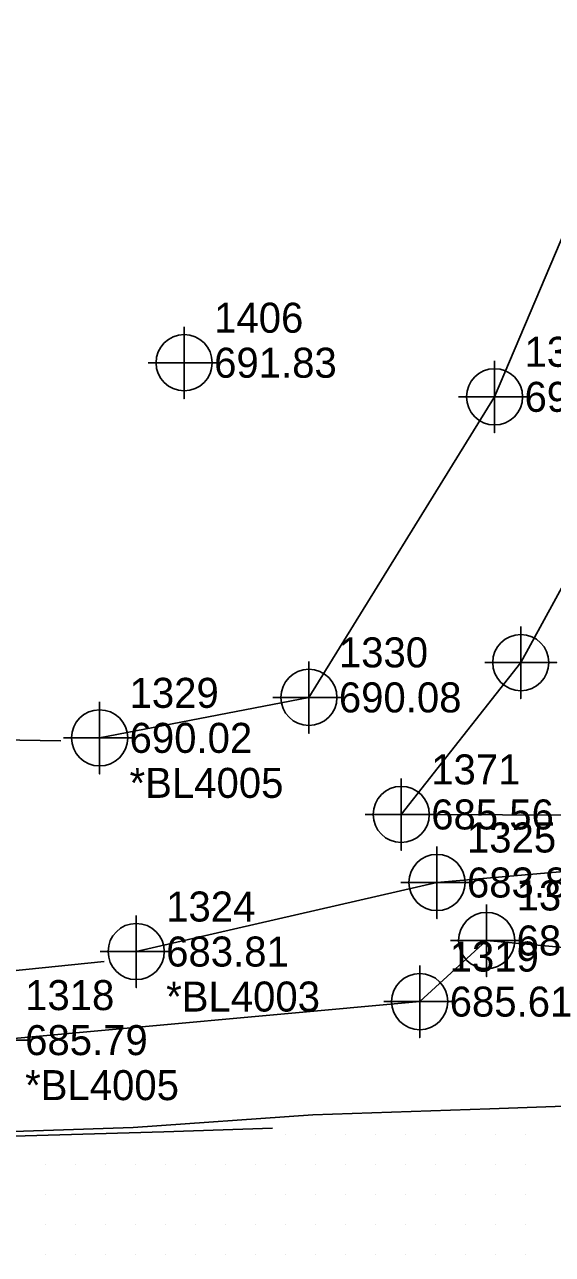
# Model space of a CAD drawing. Extents: x 1755643 to 1760494, y 736519 to 737621.
# Drawn here: x 1759022 to 1759066, y 737021.2 to 737123.7 of the extents above; entities that cross this region are included whole.
import ezdxf

# ---------------------------------------------------------------- set-up
doc = ezdxf.new("R2010")
doc.units = 0
for name, color, linetype in [('Exist Horizontal Alignment Curve and Spiral Data', 7, 'Continuous'), ('Exist Horizontal Alignment Direction Label', 7, 'Continuous'), ('Exist Railroads Standard Gauge', 7, 'Continuous'), ('Exist Roads EOT', 7, 'Continuous'), ('Old_Level_1', 7, 'Continuous'), ('Old_Level_10', 7, 'Continuous'), ('Old_Level_2', 7, 'Continuous'), ('Old_Level_3', 7, 'Continuous'), ('Prop Dimension', 7, 'Continuous'), ('Prop EOT Dash', 7, 'Continuous'), ('Prop Horizontal Alignment Direction Label', 7, 'Continuous'), ('Prop Lane Lines', 7, 'Continuous'), ('Prop Paved Shoulder', 7, 'Continuous'), ('Scratch_Level_1', 7, 'Continuous'), ('Scratch_Level_2', 7, 'Continuous'), ('Scratch_Level_5', 7, 'Continuous'), ('Scratch_Level_9', 7, 'Continuous')]:
    doc.layers.add(name, color=color, linetype=linetype)

msp = doc.modelspace()

# ---------------------------------------------------------------- linework, layer by layer
at = {"layer": 'Exist Horizontal Alignment Curve and Spiral Data'}
msp.add_lwpolyline([(1759035.3, 737098.53), (1759035.3, 737092.53), (1759035.3, 737095.53), (1759038.3, 737095.53), (1759032.3, 737095.53)], dxfattribs=at)
msp.add_circle((1759035.3, 737095.53), 2.34, dxfattribs=at)
at = {"layer": 'Exist Railroads Standard Gauge'}
for points in [[(1758977.85, 737203.59), (1758987.5, 737179.86), (1758991.58, 737151.56), (1758993.69, 737140.49), (1758995.27, 737131.26), (1758994.94, 737115.25), (1758984.91, 737087.23), (1758984.77, 737081.67), (1758987.54, 737075.38), (1758993.17, 737069.59), (1759001.68, 737066.26), (1759013.02, 737064.22), (1759025.02, 737064.03)], [(1758952.65, 737199.89), (1758952.65, 737198.86), (1758953.36, 737193.03), (1758954.04, 737179.81), (1758954.34, 737164.36), (1758955.22, 737148.98), (1758955.34, 737133.89), (1758956.84, 737119.49), (1758957.44, 737106.09), (1758959.04, 737092.09), (1758960.34, 737077.94), (1758963.11, 737068.15), (1758967.12, 737060.78), (1758972.3, 737056.45), (1758977.25, 737052.33), (1758982.37, 737047.65), (1758986.66, 737042.66), (1758993.87, 737041.05), (1759014.17, 737044.19), (1759028.62, 737045.64)]]:
    msp.add_lwpolyline(points, dxfattribs=at)
at = {"layer": 'Old_Level_10'}
for points in [[(1759056.38, 737055.23), (1759056.38, 737049.23), (1759056.38, 737052.23), (1759059.38, 737052.23), (1759053.38, 737052.23)], [(1759031.3, 737049.48), (1759031.3, 737043.48), (1759031.3, 737046.48), (1759034.3, 737046.48), (1759028.3, 737046.48)]]:
    msp.add_lwpolyline(points, dxfattribs=at)
for centre in [(1759056.38, 737052.23), (1759031.3, 737046.48)]:
    msp.add_circle(centre, 2.34, dxfattribs=at)
at = {"layer": 'Prop Dimension'}
msp.add_lwpolyline([(1759031.3, 737046.48), (1759056.38, 737052.23), (1759070.78, 737053.47), (1759077.3, 737052.76), (1759083.84, 737053.56)], dxfattribs=at)
at = {"layer": 'Prop Lane Lines'}
for points in [[(1759061.18, 737095.69), (1759061.18, 737089.69), (1759061.18, 737092.69), (1759064.18, 737092.69), (1759058.18, 737092.69)], [(1759063.37, 737073.55), (1759063.37, 737067.55), (1759063.37, 737070.55), (1759066.37, 737070.55), (1759060.37, 737070.55)], [(1759045.7, 737070.65), (1759045.7, 737064.65), (1759045.7, 737067.65), (1759048.7, 737067.65), (1759042.7, 737067.65)], [(1759028.25, 737067.28), (1759028.25, 737061.28), (1759028.25, 737064.28), (1759031.25, 737064.28), (1759025.25, 737064.28)], [(1759053.4, 737060.9), (1759053.4, 737054.9), (1759053.4, 737057.9), (1759056.4, 737057.9), (1759050.4, 737057.9)], [(1759060.52, 737050.4), (1759060.52, 737044.4), (1759060.52, 737047.4), (1759063.52, 737047.4), (1759057.52, 737047.4)], [(1759054.94, 737045.31), (1759054.94, 737039.31), (1759054.94, 737042.31), (1759057.94, 737042.31), (1759051.94, 737042.31)], [(1759019.54, 737042.1), (1759019.54, 737036.1), (1759019.54, 737039.1), (1759022.54, 737039.1), (1759016.54, 737039.1)]]:
    msp.add_lwpolyline(points, dxfattribs=at)
for centre in [(1759061.18, 737092.69), (1759063.37, 737070.55), (1759045.7, 737067.65), (1759028.25, 737064.28), (1759053.4, 737057.9), (1759060.52, 737047.4), (1759054.94, 737042.31)]:
    msp.add_circle(centre, 2.34, dxfattribs=at)
at = {"layer": 'Scratch_Level_1'}
for points in [[(1758946.45, 737118.43), (1758948.41, 737103.29), (1758951, 737088.64), (1758952.66, 737081.78), (1758954.27, 737073.73), (1758955.5, 737069.37), (1758959.45, 737056.09), (1758960.99, 737052.37), (1758963.72, 737047.71), (1758966.19, 737043.8), (1758969.77, 737040.29), (1758975.25, 737034.93), (1758977.98, 737032.41), (1758980.02, 737031.2), (1758982.04, 737030.71), (1758984.04, 737030.7), (1758986.04, 737030.8), (1759001.04, 737030.78), (1759016.06, 737031.31), (1759031.05, 737031.82), (1759046.03, 737032.89), (1759060.8, 737033.37)], [(1759245.74, 737039.35), (1759243.9, 737039.09), (1759228.95, 737038.55), (1759213.99, 737037.99), (1759199.03, 737037.38), (1759184.08, 737036.79), (1759169.11, 737036.29), (1759154.14, 737035.74), (1759140.16, 737035.36), (1759125.18, 737034.91), (1759110.19, 737034.39), (1759095.21, 737033.87), (1759083.32, 737033.73), (1759067.8, 737033.62), (1759060.8, 737033.37)]]:
    msp.add_lwpolyline(points, dxfattribs=at)
at = {"layer": 'Scratch_Level_2'}
for p, q in [((1759043.75, 737031.25), (1759043.75, 737031.25)), ((1759046.25, 737031.25), (1759046.25, 737031.25)), ((1759048.75, 737031.25), (1759048.75, 737031.25)), ((1759051.25, 737031.25), (1759051.25, 737031.25)), ((1759053.75, 737031.25), (1759053.75, 737031.25)), ((1759056.25, 737031.25), (1759056.25, 737031.25)), ((1759058.75, 737031.25), (1759058.75, 737031.25)), ((1759061.25, 737031.25), (1759061.25, 737031.25)), ((1759063.75, 737031.25), (1759063.75, 737031.25)), ((1759023.75, 737028.75), (1759023.75, 737028.75)), ((1759026.25, 737028.75), (1759026.25, 737028.75)), ((1759028.75, 737028.75), (1759028.75, 737028.75)), ((1759031.25, 737028.75), (1759031.25, 737028.75)), ((1759033.75, 737028.75), (1759033.75, 737028.75)), ((1759036.25, 737028.75), (1759036.25, 737028.75)), ((1759038.75, 737028.75), (1759038.75, 737028.75)), ((1759041.25, 737028.75), (1759041.25, 737028.75)), ((1759043.75, 737028.75), (1759043.75, 737028.75)), ((1759046.25, 737028.75), (1759046.25, 737028.75)), ((1759048.75, 737028.75), (1759048.75, 737028.75)), ((1759051.25, 737028.75), (1759051.25, 737028.75)), ((1759053.75, 737028.75), (1759053.75, 737028.75)), ((1759056.25, 737028.75), (1759056.25, 737028.75)), ((1759058.75, 737028.75), (1759058.75, 737028.75)), ((1759061.25, 737028.75), (1759061.25, 737028.75)), ((1759063.75, 737028.75), (1759063.75, 737028.75)), ((1759023.75, 737026.25), (1759023.75, 737026.25)), ((1759026.25, 737026.25), (1759026.25, 737026.25)), ((1759028.75, 737026.25), (1759028.75, 737026.25)), ((1759031.25, 737026.25), (1759031.25, 737026.25)), ((1759033.75, 737026.25), (1759033.75, 737026.25)), ((1759036.25, 737026.25), (1759036.25, 737026.25)), ((1759038.75, 737026.25), (1759038.75, 737026.25)), ((1759041.25, 737026.25), (1759041.25, 737026.25)), ((1759043.75, 737026.25), (1759043.75, 737026.25)), ((1759046.25, 737026.25), (1759046.25, 737026.25)), ((1759048.75, 737026.25), (1759048.75, 737026.25)), ((1759051.25, 737026.25), (1759051.25, 737026.25)), ((1759053.75, 737026.25), (1759053.75, 737026.25)), ((1759056.25, 737026.25), (1759056.25, 737026.25)), ((1759058.75, 737026.25), (1759058.75, 737026.25)), ((1759061.25, 737026.25), (1759061.25, 737026.25)), ((1759063.75, 737026.25), (1759063.75, 737026.25)), ((1759023.75, 737023.75), (1759023.75, 737023.75)), ((1759026.25, 737023.75), (1759026.25, 737023.75)), ((1759028.75, 737023.75), (1759028.75, 737023.75)), ((1759031.25, 737023.75), (1759031.25, 737023.75)), ((1759033.75, 737023.75), (1759033.75, 737023.75)), ((1759036.25, 737023.75), (1759036.25, 737023.75)), ((1759038.75, 737023.75), (1759038.75, 737023.75)), ((1759041.25, 737023.75), (1759041.25, 737023.75)), ((1759043.75, 737023.75), (1759043.75, 737023.75)), ((1759046.25, 737023.75), (1759046.25, 737023.75)), ((1759048.75, 737023.75), (1759048.75, 737023.75)), ((1759051.25, 737023.75), (1759051.25, 737023.75)), ((1759053.75, 737023.75), (1759053.75, 737023.75)), ((1759056.25, 737023.75), (1759056.25, 737023.75)), ((1759058.75, 737023.75), (1759058.75, 737023.75)), ((1759061.25, 737023.75), (1759061.25, 737023.75)), ((1759063.75, 737023.75), (1759063.75, 737023.75)), ((1759023.75, 737021.25), (1759023.75, 737021.25)), ((1759026.25, 737021.25), (1759026.25, 737021.25)), ((1759028.75, 737021.25), (1759028.75, 737021.25)), ((1759031.25, 737021.25), (1759031.25, 737021.25)), ((1759033.75, 737021.25), (1759033.75, 737021.25)), ((1759036.25, 737021.25), (1759036.25, 737021.25)), ((1759038.75, 737021.25), (1759038.75, 737021.25)), ((1759041.25, 737021.25), (1759041.25, 737021.25)), ((1759043.75, 737021.25), (1759043.75, 737021.25)), ((1759046.25, 737021.25), (1759046.25, 737021.25)), ((1759048.75, 737021.25), (1759048.75, 737021.25)), ((1759051.25, 737021.25), (1759051.25, 737021.25)), ((1759053.75, 737021.25), (1759053.75, 737021.25)), ((1759056.25, 737021.25), (1759056.25, 737021.25)), ((1759058.75, 737021.25), (1759058.75, 737021.25)), ((1759061.25, 737021.25), (1759061.25, 737021.25)), ((1759063.75, 737021.25), (1759063.75, 737021.25))]:
    msp.add_line(p, q, dxfattribs=at)
at = {"layer": 'Scratch_Level_5'}
msp.add_lwpolyline([(1759042.66, 737031.76), (1759033.61, 737031.46), (1759022.04, 737031.14), (1759010.71, 737030.82), (1759001.35, 737030.49), (1758991.38, 737030.27), (1758989.41, 737030.16)], dxfattribs=at)
at = {"layer": 'Scratch_Level_9'}
for points in [[(1759028.25, 737064.28), (1759045.7, 737067.65), (1759061.18, 737092.69), (1759069.23, 737111.66), (1759085.58, 737141.98), (1759096.14, 737171.88)], [(1759114.24, 737167.89), (1759096.37, 737128.92), (1759076.67, 737094.82), (1759063.37, 737070.55), (1759053.4, 737057.9), (1759070.29, 737057.83), (1759078.13, 737065.6), (1759087.49, 737092.17), (1759101.52, 737116.77), (1759113.5, 737140.74), (1759123.73, 737160.91)], [(1759019.54, 737039.1), (1759054.94, 737042.31), (1759060.52, 737047.4), (1759089.18, 737044.8), (1759122.46, 737045.98), (1759117.81, 737052.84), (1759121.45, 737059.32)]]:
    msp.add_lwpolyline(points, dxfattribs=at)

# ---------------------------------------------------------------- texts
at = {"layer": 'Exist Horizontal Alignment Direction Label'}
for p in [(1759030.75, 737059.28), (1759022.04, 737034.1)]:
    msp.add_text('*BL4005', height=2.5, dxfattribs=at).set_placement(p)
at = {"layer": 'Exist Roads EOT'}
msp.add_text('1406', height=2.5, dxfattribs=at).set_placement((1759037.8, 737098.03))
at = {"layer": 'Old_Level_1'}
for s, p in [('1325', (1759058.88, 737054.73)), ('1324', (1759033.8, 737048.98))]:
    msp.add_text(s, height=2.5, dxfattribs=at).set_placement(p)
at = {"layer": 'Old_Level_2'}
for s, p in [('683.83', (1759058.88, 737050.98)), ('683.81', (1759033.8, 737045.23))]:
    msp.add_text(s, height=2.5, dxfattribs=at).set_placement(p)
at = {"layer": 'Old_Level_3'}
for s, p in [('691.93', (1759063.68, 737091.44)), ('690.08', (1759048.2, 737066.4)), ('690.02', (1759030.75, 737063.03)), ('685.56', (1759055.9, 737056.65)), ('684.79', (1759063.02, 737046.15)), ('685.61', (1759057.44, 737041.06)), ('685.79', (1759022.04, 737037.85))]:
    msp.add_text(s, height=2.5, dxfattribs=at).set_placement(p)
at = {"layer": 'Prop EOT Dash'}
for s, p in [('1331', (1759063.68, 737095.19)), ('1330', (1759048.2, 737070.15)), ('1329', (1759030.75, 737066.78)), ('1371', (1759055.9, 737060.4)), ('1320', (1759063.02, 737049.9)), ('1319', (1759057.44, 737044.81)), ('1318', (1759022.04, 737041.6))]:
    msp.add_text(s, height=2.5, dxfattribs=at).set_placement(p)
at = {"layer": 'Prop Horizontal Alignment Direction Label'}
msp.add_text('*BL4003', height=2.5, dxfattribs=at).set_placement((1759033.8, 737041.48))
at = {"layer": 'Prop Paved Shoulder'}
msp.add_text('691.83', height=2.5, dxfattribs=at).set_placement((1759037.8, 737094.28))

doc.saveas('drawing.dxf')
